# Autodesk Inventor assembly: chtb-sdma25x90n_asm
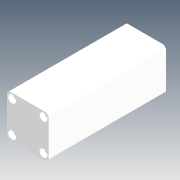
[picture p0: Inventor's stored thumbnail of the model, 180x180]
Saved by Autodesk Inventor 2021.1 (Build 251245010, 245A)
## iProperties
Company: Microsoft
Created: 2018-05
Part Number: chtb-sdma25x90n_asm
Description: STEP AP214
Document SubType Name: Assembly
Designer: user
Title: chtb-sdma25x90n_asm.STEP
Author: Windows
Revision Number: ÈÎºÎ
Sending System: SolidWorks 2015
Preprocessor: SwSTEP 2.0
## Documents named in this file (4)
- D:\Vault_2016\Projekty\Clamptek\Hydraulic\CHTB\CHTB-25\Inventor\chtb-sdma25x90n\chtb-sdma25x90n_asm.iam
- D:\Vault_2016\Projekty\Clamptek\Hydraulic\CHTB\CHTB-25\Inventor\chtb-sdma25x90n\CHTB-25QG.ipt
- D:\Vault_2016\Projekty\Clamptek\Hydraulic\CHTB\CHTB-25\Inventor\chtb-sdma25x90n\CHTB-SDMA25X90NBT.ipt
- D:\Vault_2016\Projekty\Clamptek\Hydraulic\CHTB\CHTB-25\Inventor\chtb-sdma25x90n\CHTB-SDMA25X90NHSG.ipt
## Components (3 placed, 3 different names)
1. CHTB-25QG_1
2. CHTB-SDMA25X90NBT_2
3. CHTB-SDMA25X90NHSG_3
